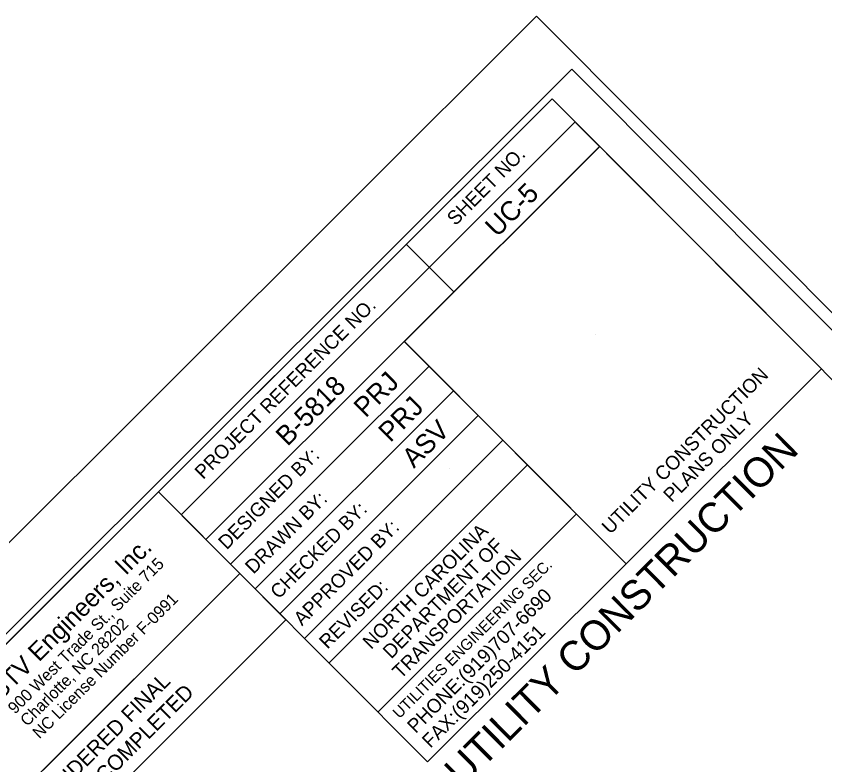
# Model space of a CAD drawing. Extents: x 1439200 to 1641361, y 392889 to 606444.
# Drawn here: x 1640975.9 to 1641092, y 393568.3 to 393675.8 of the extents above; entities that cross this region are included whole.
import ezdxf

# ---------------------------------------------------------------- set-up
doc = ezdxf.new("R2010")
doc.units = 0
for name, color, linetype in [('Old_Level_60', 7, 'Continuous'), ('Sheet Data Field CELL', 7, 'Continuous'), ('Sheet Plot Border Inside CELL', 7, 'Continuous'), ('Sheet Plot Border Outside CELL', 7, 'Continuous'), ('Sheet Sticker Exception Certification CELL', 7, 'Continuous'), ('UC Plan Sheet 34 CELL', 7, 'Continuous')]:
    doc.layers.add(name, color=color, linetype=linetype)

msp = doc.modelspace()

# ---------------------------------------------------------------- linework, layer by layer
at = {"layer": 'Old_Level_60'}
msp.add_lwpolyline([(1640939.64, 393550.94), (1640996.29, 393607.45), (1641007.98, 393595.72), (1640951.33, 393539.22)], close=True, dxfattribs=at)
at = {"layer": 'Sheet Plot Border Inside CELL'}
msp.add_lwpolyline([(1641055.7, 393668.15), (1640583.75, 393197.39), (1640881.8, 392898.58), (1641353.75, 393369.35)], close=True, dxfattribs=at)
at = {"layer": 'Sheet Plot Border Outside CELL'}
msp.add_lwpolyline([(1641050.63, 393675.78), (1640573.73, 393200.07), (1640884.46, 392888.55), (1641361.37, 393364.26)], close=True, dxfattribs=at)
at = {"layer": 'Sheet Sticker Exception Certification CELL'}
for p, q in [((1640951.33, 393539.22), (1641007.98, 393595.72)), ((1641007.98, 393595.72), (1641014.62, 393589.07)), ((1641014.62, 393589.07), (1640957.97, 393532.56))]:
    msp.add_line(p, q, dxfattribs=at)
at = {"layer": 'UC Plan Sheet 34 CELL'}
for p, q in [((1640999.56, 393604.16), (1641056.16, 393660.61)), ((1641047.44, 393648.38), (1641047.44, 393648.38)), ((1641031.95, 393643.01), (1641038.76, 393636.18)), ((1641059.03, 393630.12), (1641059.03, 393630.12)), ((1641006.64, 393597.06), (1641035.17, 393625.52)), ((1641010.18, 393593.52), (1641038.71, 393621.97)), ((1641027.56, 393621.47), (1641027.56, 393621.47)), ((1641019.12, 393620.14), (1641019.12, 393620.14)), ((1641013.72, 393589.97), (1641042.25, 393618.43)), ((1641031.1, 393617.92), (1641031.1, 393617.92)), ((1641017.26, 393586.42), (1641045.79, 393614.88)), ((1641034.64, 393614.37), (1641034.64, 393614.37)), ((1641020.8, 393582.87), (1641049.33, 393611.33)), ((1641038.17, 393610.82), (1641038.17, 393610.82)), ((1641027.82, 393575.83), (1641056.35, 393604.29))]:
    msp.add_line(p, q, dxfattribs=at)
msp.add_lwpolyline([(1641052.88, 393663.9), (1640628.08, 393240.17), (1640924.7, 392942.81), (1641349.49, 393366.54)], close=True, dxfattribs=at)
for points in [[(1640996.29, 393607.45), (1641052.88, 393663.9), (1641059.68, 393657.08)], [(1641059.68, 393657.08), (1641003.09, 393600.63), (1640996.29, 393607.45)], [(1641091.55, 393625.13), (1641063.49, 393597.14), (1641031.63, 393629.07), (1641059.7, 393657.07)], [(1641059.7, 393657.07), (1641091.55, 393625.13)], [(1641031.62, 393629.08), (1641063.49, 393597.14), (1641034.96, 393568.68), (1640996.29, 393607.45)]]:
    msp.add_lwpolyline(points, dxfattribs=at)

# ---------------------------------------------------------------- texts
at = {"layer": 'Old_Level_60'}
for s, height, p in [('STV Engineers, Inc.', 2.6, (1640973.66, 393577.49)), ('900 West Trade St., Suite 715', 1.7, (1640975.68, 393575.46)), ('NC License Number F-0991', 1.7, (1640979.21, 393571.92)), ('Charlotte, NC 28202', 1.7, (1640977.45, 393573.69))]:
    msp.add_text(s, height=height, rotation=44.9279, dxfattribs=at).set_placement(p)
at = {"layer": 'Sheet Data Field CELL'}
for s, p in [('UC-5', (1641044.95, 393643.93)), ('B-5818', (1641014.85, 393613.9)), ('PRJ', (1641026.06, 393618)), ('PRJ', (1641029.6, 393614.45)), ('ASV', (1641033, 393610.76))]:
    msp.add_text(s, height=2.8, rotation=44.9279, dxfattribs=at).set_placement(p)
at = {"layer": 'Sheet Sticker Exception Certification CELL'}
for s, p in [('DOCUMENT NOT CONSIDERED FINAL', (1640960.22, 393542.24)), ('UNLESS ALL SIGNATURES COMPLETED', (1640961.27, 393538.31))]:
    msp.add_text(s, height=2.2, rotation=44.9279, dxfattribs=at).set_placement(p)
at = {"layer": 'UC Plan Sheet 34 CELL'}
for s, height, p in [('SHEET NO.', 2.005, (1641038.96, 393645.59)), ('PROJECT REFERENCE NO.', 2.0046, (1641002.71, 393609.17)), ('UTILITY CONSTRUCTION', 2.0046, (1641061.2, 393601.28)), ('PLANS ONLY', 2.005, (1641070.04, 393605.85)), ('UTILITY CONSTRUCTION', 4.25, (1641040.01, 393564.89)), ('DESIGNED BY:', 2.0046, (1641006.1, 393599.07)), ('DRAWN BY:', 2.005, (1641009.96, 393595.56)), ('CHECKED BY:', 2.0046, (1641013.57, 393591.97)), ('APPROVED BY:', 2.0046, (1641016.93, 393588.12)), ('NORTH CAROLINA', 2.0046, (1641026.85, 393584.74)), ('DEPARTMENT OF', 2.0046, (1641029.74, 393583.38)), ('TRANSPORTATION', 2.0046, (1641031.12, 393580.51)), ('UTILITIES ENGINEERING SEC.', 1.6037, (1641030.91, 393574.81)), ('REVISED:', 2.005, (1641020.59, 393584.79)), ('PHONE:(919)707-6690', 2.0046, (1641033.25, 393572.69)), ('FAX:(919)250-4151', 2.0046, (1641035.37, 393570.56))]:
    msp.add_text(s, height=height, rotation=44.9279, dxfattribs=at).set_placement(p)

doc.saveas('drawing.dxf')
